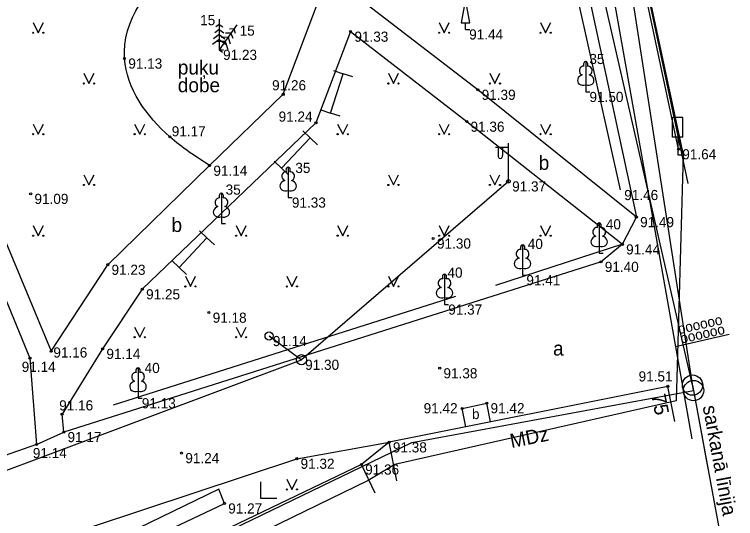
# Model space of a CAD drawing. Extents: x 634272 to 634544, y 247463 to 247653.
# Drawn here: x 634438.83 to 634474.36, y 247516.06 to 247540.9 of the extents above; entities that cross this region are included whole.
import ezdxf

# ---------------------------------------------------------------- set-up
doc = ezdxf.new("R2010")
doc.units = 0
for name, color, linetype in [('APGR_ELEM_####_####_#', 7, 'Continuous'), ('APGR_SARK_####_####_#', 7, 'Continuous'), ('APGR_SARK_####_TKST_#', 7, 'Continuous'), ('APGS_ELEM_####_####_#', 7, 'Continuous'), ('APGS_VADP_ZSPR_####_#', 7, 'Continuous'), ('BUVE_BDET_####_####_#', 7, 'Continuous'), ('BUVE_BDET_####_TKST_#', 7, 'Continuous'), ('BUVE_EKAS_####_####_#', 7, 'Continuous'), ('BUVE_EKAS_ADRS_TKST_#', 7, 'Continuous'), ('BUVE_EKAS_RAKS_TKST_#', 7, 'Continuous'), ('BUVE_SOLS_####_####_#', 7, 'Continuous'), ('CELI_CAPM_####_####_#', 7, 'Continuous'), ('CELI_CMAL_####_####_#', 7, 'Continuous'), ('CELI_CSEG_####_TKST_#', 7, 'Continuous'), ('CELI_ELEM_####_####_#', 7, 'Continuous'), ('CELI_SEGL_####_####_#', 7, 'Continuous'), ('ELEK_ELEM_####_####_#', 7, 'Continuous'), ('ELEK_STUT_####_####_#', 7, 'Continuous'), ('ELEK_VADV_ZSPR_####_#', 7, 'Continuous'), ('NORB_ZOGS_KOKA_####_#', 7, 'Continuous'), ('NORB_ZOGS_ZMET_####_#', 7, 'Continuous'), ('RAMI_UZMR_####_####_#', 7, 'Continuous'), ('RELJ_AATZ_####_TKST_#', 7, 'Continuous'), ('RELJ_ELEM_####_####_#', 7, 'Continuous'), ('ROBZ_PROJ_####_####_#', 7, 'Continuous'), ('ROBZ_UZMR_####_####_#', 7, 'Continuous'), ('SAKK_IZVK_####_TKST_#', 7, 'Continuous'), ('SAKK_KKAN_####_####_#', 7, 'Continuous'), ('TERT_DIAM_####_TKST_#', 7, 'Continuous'), ('TERT_DZOG_####_####_#', 7, 'Continuous'), ('TERT_ELEM_####_####_#', 7, 'Continuous'), ('TERT_IZMT_####_TKST_#', 7, 'Continuous'), ('TERT_KONT_####_####_#', 7, 'Continuous')]:
    doc.layers.add(name, color=color, linetype=linetype)

msp = doc.modelspace()

# ---------------------------------------------------------------- linework, layer by layer
at = {"layer": 'APGR_ELEM_####_####_#'}
for centre in [(634472.24, 247522.64), (634472.29, 247522.37)]:
    msp.add_circle(centre, 0.5, dxfattribs=at)
at = {"layer": 'APGR_SARK_####_####_#'}
for p, q in [((634472.239, 247522.641), (634452.431, 247609.249)), ((634472.285, 247522.369), (634472.997, 247518.53))]:
    msp.add_line(p, q, dxfattribs=at)
msp.add_lwpolyline([(634472.24, 247522.64), (634472.285, 247522.369)], dxfattribs=at)
at = {"layer": 'APGS_ELEM_####_####_#'}
for p, q in [((634463.166, 247532.679), (634463.166, 247534.562)), ((634463.166, 247534.346), (634462.531, 247534.341)), ((634462.666, 247534.342), (634462.666, 247533.95)), ((634462.876, 247534.344), (634462.876, 247533.95))]:
    msp.add_line(p, q, dxfattribs=at)
msp.add_circle((634463.166, 247532.679), 0.09, dxfattribs=at)
msp.add_ellipse((634462.771, 247533.95), major_axis=(0, 0.151), ratio=0.695971, start_param=1.570796, end_param=4.712389, dxfattribs=at)
at = {"layer": 'APGS_VADP_ZSPR_####_#'}
msp.add_lwpolyline([(634463.166, 247532.679), (634452.967, 247523.892)], dxfattribs=at)
at = {"layer": 'BUVE_BDET_####_####_#'}
for p, q in [((634462.287, 247520.826), (634462.101, 247521.751)), ((634461.07, 247520.582), (634460.888, 247521.491))]:
    msp.add_line(p, q, dxfattribs=at)
for points in [[(634460.888, 247521.491), (634462.101, 247521.751)], [(634442.961, 247513.867), (634449.175, 247516.814), (634448.89, 247517.508), (634442.673, 247514.485), (634442.961, 247513.867)]]:
    msp.add_lwpolyline(points, dxfattribs=at)
at = {"layer": 'BUVE_EKAS_####_####_#'}
for p, q in [((634471.371, 247520.855), (634471.025, 247522.579)), ((634457.668, 247517.931), (634457.288, 247519.823)), ((634456.604, 247517.313), (634455.924, 247518.731))]:
    msp.add_line(p, q, dxfattribs=at)
for points in [[(634471.025, 247522.579), (634457.288, 247519.823)], [(634455.924, 247518.731), (634433.316, 247507.888)]]:
    msp.add_lwpolyline(points, dxfattribs=at)
at = {"layer": 'BUVE_SOLS_####_####_#'}
for p, q in [((634454.542, 247538.134), (634455.018, 247537.981)), ((634455.494, 247537.828), (634455.018, 247537.981)), ((634453.919, 247536.196), (634454.395, 247536.043)), ((634454.871, 247535.89), (634454.395, 247536.043)), ((634454.871, 247535.89), (634454.395, 247536.043)), ((634453.041, 247535.164), (634453.403, 247534.82)), ((634453.765, 247534.476), (634453.403, 247534.82)), ((634451.629, 247533.678), (634451.991, 247533.334)), ((634452.353, 247532.99), (634451.991, 247533.334)), ((634447.947, 247530.237), (634448.312, 247529.896)), ((634448.677, 247529.555), (634448.312, 247529.896)), ((634446.577, 247528.771), (634446.942, 247528.43)), ((634447.307, 247528.089), (634446.942, 247528.43))]:
    msp.add_line(p, q, dxfattribs=at)
for points in [[(634454.395, 247536.043), (634455.018, 247537.981)], [(634451.991, 247533.334), (634453.403, 247534.82)], [(634446.942, 247528.43), (634448.312, 247529.896)]]:
    msp.add_lwpolyline(points, dxfattribs=at)
at = {"layer": 'CELI_CAPM_####_####_#'}
for points in [[(634463.467, 247557.413), (634465.341, 247550.039), (634461.38, 247548.991), (634462.172, 247545.409), (634466.133, 247546.478), (634469.47, 247530.921)], [(634468.781, 247529.576), (634467.729, 247528.716)], [(634467.729, 247528.716), (634441.257, 247520.329)], [(634439.91, 247519.719), (634429.724, 247516.149)]]:
    msp.add_lwpolyline(points, dxfattribs=at)
at = {"layer": 'CELI_CMAL_####_####_#'}
for points in [[(634472.031, 247532.571), (634469.381, 247545.11), (634466.419, 247558.939), (634461.107, 247582.724), (634454.551, 247609.343)], [(634448.962, 247545.329), (634432.293, 247544.34), (634440.634, 247524.306)], [(634440.634, 247524.306), (634443.425, 247528.573), (634448.443, 247533.452), (634452.075, 247536.966), (634453.755, 247541.439)], [(634469.47, 247530.921), (634461.663, 247537.193), (634455.996, 247541.547)], [(634455.391, 247540.056), (634453.685, 247535.561), (634445.128, 247527.364), (634443.172, 247524.429), (634441.171, 247521.203)], [(634455.391, 247540.056), (634461.114, 247535.622), (634468.781, 247529.576)], [(634435.216, 247534.576), (634439.591, 247523.962)], [(634439.591, 247523.962), (634439.91, 247519.719)], [(634441.257, 247520.329), (634441.171, 247521.203)], [(634432.152, 247511.13), (634442.666, 247515.679), (634452.74, 247519.016), (634457.288, 247519.823)]]:
    msp.add_lwpolyline(points, dxfattribs=at)
at = {"layer": 'CELI_ELEM_####_####_#'}
for p, q in [((634471.76, 247535.832), (634471.26, 247535.832)), ((634471.26, 247534.863), (634471.26, 247535.832)), ((634471.76, 247534.863), (634471.76, 247535.832)), ((634471.76, 247534.863), (634471.26, 247534.863)), ((634471.514, 247534.863), (634471.514, 247533.985)), ((634471.514, 247533.985), (634471.829, 247533.985))]:
    msp.add_line(p, q, dxfattribs=at)
at = {"layer": 'CELI_SEGL_####_####_#'}
for points in [[(634468.781, 247529.576), (634469.47, 247530.921)], [(634439.91, 247519.719), (634441.257, 247520.329)]]:
    msp.add_lwpolyline(points, dxfattribs=at)
at = {"layer": 'ELEK_ELEM_####_####_#'}
for centre, radius in [((634451.373, 247525.062), 0.2), ((634452.967, 247523.892), 0.25)]:
    msp.add_circle(centre, radius, dxfattribs=at)
at = {"layer": 'ELEK_STUT_####_####_#'}
msp.add_lwpolyline([(634451.373, 247525.062), (634452.967, 247523.892)], dxfattribs=at)
at = {"layer": 'ELEK_VADV_ZSPR_####_#'}
msp.add_lwpolyline([(634425.403, 247513.565), (634452.967, 247523.892)], dxfattribs=at)
at = {"layer": 'NORB_ZOGS_KOKA_####_#'}
msp.add_lwpolyline([(634457.288, 247519.823), (634455.924, 247518.731)], dxfattribs=at)
at = {"layer": 'NORB_ZOGS_ZMET_####_#'}
msp.add_lwpolyline([(634471.548, 247534.262), (634466.407, 247558.475)], dxfattribs=at)
at = {"layer": 'RAMI_UZMR_####_####_#'}
msp.add_lwpolyline([(634466.614, 247558.36), (634469.076, 247546.545), (634471.781, 247533.982), (634471.429, 247521.859), (634457.577, 247518.735), (634456.257, 247517.942), (634433.742, 247506.986), (634428.158, 247503.509), (634420.457, 247500.517), (634407.71, 247496.821), (634397.043, 247493.687), (634395.968, 247498.053), (634390.559, 247517.942), (634387.41, 247527.318), (634427.834, 247538.059), (634425.364, 247546.393), (634376.048, 247532.596), (634371.988, 247530.992)], dxfattribs=at)
at = {"layer": 'RELJ_ELEM_####_####_#'}
for centre in [(634455.391, 247540.056), (634444.251, 247538.733), (634452.075, 247536.966), (634461.663, 247537.193), (634453.685, 247535.561), (634461.114, 247535.622), (634446.479, 247534.873), (634471.548, 247534.262), (634448.443, 247533.452), (634439.626, 247532.065), (634469.47, 247530.921), (634459.461, 247529.864), (634468.781, 247529.576), (634443.425, 247528.573), (634467.729, 247528.716), (634445.128, 247527.364), (634448.409, 247526.212), (634440.634, 247524.306), (634443.172, 247524.429), (634439.591, 247523.962), (634459.78, 247523.472), (634471.025, 247522.579), (634462.101, 247521.751), (634460.888, 247521.491), (634441.171, 247521.203), (634441.257, 247520.329), (634439.91, 247519.719), (634457.288, 247519.823), (634447.06, 247519.294), (634452.74, 247519.016), (634455.924, 247518.731), (634449.175, 247516.814)]:
    msp.add_circle(centre, 0.05, dxfattribs=at)
at = {"layer": 'ROBZ_PROJ_####_####_#'}
msp.add_lwpolyline([(634472.285, 247522.369), (634466.305, 247560.948)], dxfattribs=at)
at = {"layer": 'ROBZ_UZMR_####_####_#'}
for points in [[(634458.415, 247519.805), (634472.285, 247522.369)], [(634472.285, 247522.369), (634473.767, 247514.38)], [(634434.292, 247508.17), (634458.415, 247519.805)]]:
    msp.add_lwpolyline(points, dxfattribs=at)
at = {"layer": 'SAKK_IZVK_####_TKST_#'}
msp.add_line((634471.394, 247524.543), (634474.052, 247525.142), dxfattribs=at)
at = {"layer": 'SAKK_KKAN_####_####_#'}
msp.add_lwpolyline([(634452.888, 247611.435), (634454.857, 247603.576), (634466.565, 247551.758), (634472.201, 247519.993)], dxfattribs=at)
at = {"layer": 'TERT_DZOG_####_####_#'}
for points in [[(634468.687, 247532.255), (634465.596, 247546.127)], [(634468.781, 247529.576), (634462.526, 247527.553)], [(634460.556, 247526.999), (634443.688, 247521.659)]]:
    msp.add_lwpolyline(points, dxfattribs=at)
at = {"layer": 'TERT_ELEM_####_####_#'}
for p, q in [((634448.921, 247540.661), (634448.921, 247539.161)), ((634439.75, 247540.5), (634440, 247540)), ((634440, 247540), (634440.25, 247540.5)), ((634448.921, 247540.161), (634448.705, 247540.003)), ((634448.921, 247540.411), (634448.745, 247540.283)), ((634448.921, 247540.411), (634449.095, 247540.283)), ((634449.781, 247540.39), (634448.921, 247539.161)), ((634448.921, 247540.161), (634449.137, 247540.003)), ((634449.638, 247540.185), (634449.42, 247540.181)), ((634449.638, 247540.185), (634449.707, 247539.98)), ((634459.75, 247540.5), (634460, 247540)), ((634460, 247540), (634460.25, 247540.5)), ((634461.048, 247540.167), (634461.048, 247540.487)), ((634461.048, 247540.167), (634461.258, 247540.167)), ((634464.75, 247540.5), (634465, 247540)), ((634465, 247540), (634465.25, 247540.5)), ((634448.921, 247539.911), (634448.643, 247539.707)), ((634448.921, 247539.911), (634449.199, 247539.707)), ((634449.495, 247539.98), (634449.227, 247539.975)), ((634449.495, 247539.98), (634449.581, 247539.727)), ((634448.921, 247539.661), (634448.589, 247539.417)), ((634449.208, 247539.571), (634448.796, 247539.561)), ((634448.921, 247539.661), (634449.255, 247539.417)), ((634449.351, 247539.775), (634449.006, 247539.768)), ((634449.208, 247539.571), (634449.341, 247539.179)), ((634449.351, 247539.775), (634449.462, 247539.449)), ((634448.921, 247539.161), (634449.121, 247539.161)), ((634448.921, 247539.161), (634449.085, 247539.046)), ((634442.25, 247538), (634442.5, 247537.5)), ((634442.5, 247537.5), (634442.75, 247538)), ((634457.25, 247538), (634457.5, 247537.5)), ((634457.5, 247537.5), (634457.75, 247538)), ((634462.25, 247538), (634462.5, 247537.5)), ((634462.5, 247537.5), (634462.75, 247538)), ((634466.975, 247537.433), (634466.975, 247537.086)), ((634466.975, 247537.086), (634467.175, 247537.086)), ((634439.75, 247535.5), (634440, 247535)), ((634440, 247535), (634440.25, 247535.5)), ((634444.75, 247535.5), (634445, 247535)), ((634445, 247535), (634445.25, 247535.5)), ((634454.75, 247535.5), (634455, 247535)), ((634455, 247535), (634455.25, 247535.5)), ((634459.75, 247535.5), (634460, 247535)), ((634460, 247535), (634460.25, 247535.5)), ((634464.75, 247535.5), (634465, 247535)), ((634465, 247535), (634465.25, 247535.5)), ((634442.25, 247533), (634442.5, 247532.5)), ((634442.5, 247532.5), (634442.75, 247533)), ((634457.25, 247533), (634457.5, 247532.5)), ((634457.5, 247532.5), (634457.75, 247533)), ((634462.25, 247533), (634462.5, 247532.5)), ((634462.5, 247532.5), (634462.75, 247533)), ((634452.312, 247532.229), (634452.312, 247531.882)), ((634452.312, 247531.882), (634452.512, 247531.882)), ((634449.023, 247530.941), (634449.023, 247530.594)), ((634449.023, 247530.594), (634449.223, 247530.594)), ((634439.75, 247530.5), (634440, 247530)), ((634440, 247530), (634440.25, 247530.5)), ((634449.75, 247530.5), (634450, 247530)), ((634450, 247530), (634450.25, 247530.5)), ((634454.75, 247530.5), (634455, 247530)), ((634455, 247530), (634455.25, 247530.5)), ((634459.75, 247530.5), (634460, 247530)), ((634460, 247530), (634460.25, 247530.5)), ((634464.75, 247530.5), (634465, 247530)), ((634465, 247530), (634465.25, 247530.5)), ((634467.639, 247529.484), (634467.639, 247529.137)), ((634467.639, 247529.137), (634467.839, 247529.137)), ((634463.865, 247528.405), (634463.865, 247528.058)), ((634447.25, 247528), (634447.5, 247527.5)), ((634447.5, 247527.5), (634447.75, 247528)), ((634452.25, 247528), (634452.5, 247527.5)), ((634452.5, 247527.5), (634452.75, 247528)), ((634457.25, 247528), (634457.5, 247527.5)), ((634457.5, 247527.5), (634457.75, 247528)), ((634463.865, 247528.058), (634464.065, 247528.058)), ((634460.017, 247526.96), (634460.017, 247526.613)), ((634460.017, 247526.613), (634460.217, 247526.613)), ((634444.75, 247525.5), (634445, 247525)), ((634445, 247525), (634445.25, 247525.5)), ((634449.75, 247525.5), (634450, 247525)), ((634450, 247525), (634450.25, 247525.5)), ((634444.916, 247522.345), (634444.916, 247521.998)), ((634444.916, 247521.998), (634445.116, 247521.998)), ((634450.957, 247517.875), (634450.957, 247517.075)), ((634452.25, 247518), (634452.5, 247517.5)), ((634452.5, 247517.5), (634452.75, 247518)), ((634450.957, 247517.075), (634451.757, 247517.075))]:
    msp.add_line(p, q, dxfattribs=at)
msp.add_lwpolyline([(634460.838, 247540.487), (634461.258, 247540.487), (634461.048, 247541.667)], close=True, dxfattribs=at)
for points in [[(634466.975, 247538.586), (634466.975, 247537.433)], [(634467.065, 247538.354), (634467.064, 247538.355)], [(634452.312, 247533.382), (634452.312, 247532.229)], [(634452.402, 247533.15), (634452.401, 247533.151)], [(634449.023, 247532.094), (634449.023, 247530.941)], [(634449.113, 247531.862), (634449.112, 247531.863)], [(634467.639, 247530.637), (634467.639, 247529.484)], [(634467.729, 247530.405), (634467.728, 247530.406)], [(634463.865, 247529.558), (634463.865, 247528.405)], [(634463.955, 247529.326), (634463.954, 247529.327)], [(634460.017, 247528.113), (634460.017, 247526.96)], [(634460.107, 247527.881), (634460.106, 247527.882)], [(634444.916, 247523.498), (634444.916, 247522.345)], [(634445.006, 247523.266), (634445.005, 247523.267)]]:
    msp.add_lwpolyline(points, dxfattribs=at)
for centre, radius in [((634439.75, 247540), 0.028), ((634440.25, 247540), 0.0263), ((634459.75, 247540), 0.028), ((634460.25, 247540), 0.0263), ((634464.75, 247540), 0.028), ((634465.25, 247540), 0.0263), ((634442.25, 247537.5), 0.028), ((634442.75, 247537.5), 0.0263), ((634457.25, 247537.5), 0.028), ((634457.75, 247537.5), 0.0263), ((634462.25, 247537.5), 0.028), ((634462.75, 247537.5), 0.0263), ((634439.75, 247535), 0.028), ((634440.25, 247535), 0.0263), ((634444.75, 247535), 0.028), ((634445.25, 247535), 0.0263), ((634454.75, 247535), 0.028), ((634455.25, 247535), 0.0263), ((634459.75, 247535), 0.028), ((634460.25, 247535), 0.0263), ((634464.75, 247535), 0.028), ((634465.25, 247535), 0.0263), ((634442.25, 247532.5), 0.028), ((634442.75, 247532.5), 0.0263), ((634457.25, 247532.5), 0.028), ((634457.75, 247532.5), 0.0263), ((634462.25, 247532.5), 0.028), ((634462.75, 247532.5), 0.0263), ((634439.75, 247530), 0.028), ((634440.25, 247530), 0.0263), ((634449.75, 247530), 0.028), ((634450.25, 247530), 0.0263), ((634454.75, 247530), 0.028), ((634455.25, 247530), 0.0263), ((634459.75, 247530), 0.028), ((634460.25, 247530), 0.0263), ((634464.75, 247530), 0.028), ((634465.25, 247530), 0.0263), ((634447.25, 247527.5), 0.028), ((634447.75, 247527.5), 0.0263), ((634452.25, 247527.5), 0.028), ((634452.75, 247527.5), 0.0263), ((634457.25, 247527.5), 0.028), ((634457.75, 247527.5), 0.0263), ((634444.75, 247525), 0.028), ((634445.25, 247525), 0.0263), ((634449.75, 247525), 0.028), ((634450.25, 247525), 0.0263), ((634452.25, 247517.5), 0.028), ((634452.75, 247517.5), 0.0263)]:
    msp.add_circle(centre, radius, dxfattribs=at)
for centre, major_axis, ratio, start_param, end_param in [((634466.975, 247538.436), (0, -0.15), 0.707107, 3.14537, 5.287485), ((634466.975, 247538.436), (0, -0.15), 0.707107, 0.995701, 3.137816), ((634466.847, 247538.141), (-0.039, -0.212), 0.861323, 3.141593, 6.283185), ((634467.103, 247538.141), (0.039, -0.212), 0.861323, 0, 3.141593), ((634466.885, 247537.679), (0.307, 0.095), 0.814445, 1.570796, 4.752015), ((634467.065, 247537.679), (-0.307, 0.095), 0.814445, 1.531171, 4.712389), ((634452.184, 247532.937), (-0.039, -0.212), 0.861323, 3.141593, 6.283185), ((634452.312, 247533.232), (0, -0.15), 0.707107, 3.14537, 5.287485), ((634452.312, 247533.232), (0, -0.15), 0.707107, 0.995701, 3.137816), ((634452.44, 247532.937), (0.039, -0.212), 0.861323, 0, 3.141593), ((634452.222, 247532.475), (0.307, 0.095), 0.814445, 1.570796, 4.752015), ((634452.402, 247532.475), (-0.307, 0.095), 0.814445, 1.531171, 4.712389), ((634449.023, 247531.944), (0, -0.15), 0.707107, 3.14537, 5.287485), ((634449.023, 247531.944), (0, -0.15), 0.707107, 0.995701, 3.137816), ((634448.895, 247531.649), (-0.039, -0.212), 0.861323, 3.141593, 6.283185), ((634449.151, 247531.649), (0.039, -0.212), 0.861323, 0, 3.141593), ((634448.933, 247531.187), (0.307, 0.095), 0.814445, 1.570796, 4.752015), ((634449.113, 247531.187), (-0.307, 0.095), 0.814445, 1.531171, 4.712389), ((634467.639, 247530.487), (0, -0.15), 0.707107, 3.14537, 5.287485), ((634467.639, 247530.487), (0, -0.15), 0.707107, 0.995701, 3.137816), ((634467.511, 247530.192), (-0.039, -0.212), 0.861323, 3.141593, 6.283185), ((634467.767, 247530.192), (0.039, -0.212), 0.861323, 0, 3.141593), ((634467.549, 247529.73), (0.307, 0.095), 0.814445, 1.570796, 4.752015), ((634467.729, 247529.73), (-0.307, 0.095), 0.814445, 1.531171, 4.712389), ((634463.865, 247529.408), (0, -0.15), 0.707107, 3.14537, 5.287485), ((634463.865, 247529.408), (0, -0.15), 0.707107, 0.995701, 3.137816), ((634463.737, 247529.113), (-0.039, -0.212), 0.861323, 3.141593, 6.283185), ((634463.993, 247529.113), (0.039, -0.212), 0.861323, 0, 3.141593), ((634463.775, 247528.651), (0.307, 0.095), 0.814445, 1.570796, 4.752015), ((634463.955, 247528.651), (-0.307, 0.095), 0.814445, 1.531171, 4.712389), ((634460.017, 247527.963), (0, -0.15), 0.707107, 3.14537, 5.287485), ((634460.017, 247527.963), (0, -0.15), 0.707107, 0.995701, 3.137816), ((634459.889, 247527.668), (-0.039, -0.212), 0.861323, 3.141593, 6.283185), ((634460.145, 247527.668), (0.039, -0.212), 0.861323, 0, 3.141593), ((634459.927, 247527.206), (0.307, 0.095), 0.814445, 1.570796, 4.752015), ((634460.107, 247527.206), (-0.307, 0.095), 0.814445, 1.531171, 4.712389), ((634444.916, 247523.348), (0, -0.15), 0.707107, 3.14537, 5.287485), ((634444.916, 247523.348), (0, -0.15), 0.707107, 0.995701, 3.137816), ((634444.788, 247523.053), (-0.039, -0.212), 0.861323, 3.141593, 6.283185), ((634445.044, 247523.053), (0.039, -0.212), 0.861323, 0, 3.141593), ((634444.826, 247522.591), (0.307, 0.095), 0.814445, 1.570796, 4.752015), ((634445.006, 247522.591), (-0.307, 0.095), 0.814445, 1.531171, 4.712389)]:
    msp.add_ellipse(centre, major_axis=major_axis, ratio=ratio, start_param=start_param, end_param=end_param, dxfattribs=at)
at = {"layer": 'TERT_KONT_####_####_#'}
msp.add_spline([(634448.443, 247533.452), (634446.479, 247534.873), (634444.251, 247538.733), (634447.111, 247543.417), (634448.673, 247544.455), (634448.962, 247545.329)], degree=3, dxfattribs=at)

# ---------------------------------------------------------------- texts
at = {"layer": 'APGR_SARK_####_TKST_#'}
msp.add_text('sarkanā līnija', height=0.7, rotation=280.5112, dxfattribs=at).set_placement((634472.736, 247521.586))
at = {"layer": 'BUVE_BDET_####_TKST_#'}
msp.add_text('b', height=0.5, dxfattribs=at).set_placement((634461.371, 247520.966))
at = {"layer": 'BUVE_EKAS_ADRS_TKST_#'}
msp.add_text('75', height=0.7, rotation=281.3444, dxfattribs=at).set_placement((634470.205, 247522.134))
at = {"layer": 'BUVE_EKAS_RAKS_TKST_#'}
msp.add_text('MDz', height=0.7, rotation=11.3444, dxfattribs=at).set_placement((634463.317, 247519.535))
at = {"layer": 'CELI_CSEG_####_TKST_#'}
for s, p in [('b', (634464.659, 247533.245)), ('b', (634446.567, 247530.184)), ('a', (634465.366, 247524.096))]:
    msp.add_text(s, height=0.7, dxfattribs=at).set_placement(p)
at = {"layer": 'RELJ_AATZ_####_TKST_#'}
for s, p in [(' 91.44', (634461.048, 247539.667)), (' 91.44', (634461.048, 247539.667)), (' 91.33', (634455.391, 247539.556)), (' 91.23', (634448.921, 247538.661)), (' 91.13', (634444.251, 247538.233)), (' 91.26', (634451.336, 247537.162)), (' 91.39', (634461.663, 247536.693)), (' 91.50', (634466.975, 247536.586)), (' 91.24', (634451.657, 247535.618)), (' 91.36', (634461.114, 247535.122)), (' 91.17', (634446.392, 247534.895)), (' 91.64', (634471.548, 247533.762)), (' 91.14', (634448.443, 247532.952)), (' 91.37', (634463.166, 247532.179)), (' 91.09', (634439.626, 247531.565)), (' 91.46', (634468.687, 247531.755)), (' 91.33', (634452.312, 247531.382)), (' 91.49', (634469.47, 247530.421)), (' 91.30', (634459.461, 247529.364)), (' 91.44', (634468.781, 247529.076)), (' 91.23', (634443.425, 247528.073)), (' 91.40', (634467.729, 247528.216)), (' 91.41', (634463.865, 247527.558)), (' 91.25', (634445.128, 247526.864)), (' 91.37', (634460.017, 247526.113)), (' 91.18', (634448.409, 247525.712)), (' 91.14', (634451.373, 247524.562)), (' 91.16', (634440.558, 247523.997)), (' 91.14', (634443.172, 247523.929)), (' 91.30', (634452.967, 247523.392)), (' 91.14', (634438.998, 247523.29)), (' 91.38', (634459.78, 247522.972)), (' 91.51', (634469.396, 247522.819)), (' 91.16', (634440.846, 247521.392)), (' 91.13', (634444.916, 247521.498)), (' 91.42', (634458.804, 247521.251)), (' 91.42', (634462.101, 247521.251)), (' 91.17', (634441.257, 247519.829)), (' 91.14', (634439.547, 247519.043)), (' 91.38', (634457.288, 247519.323)), (' 91.24', (634447.06, 247518.794)), (' 91.32', (634452.74, 247518.516)), (' 91.36', (634455.924, 247518.231)), (' 91.27', (634449.175, 247516.314))]:
    msp.add_text(s, height=0.5, dxfattribs=at).set_placement(p)
at = {"layer": 'SAKK_IZVK_####_TKST_#'}
for p in [(634471.571, 247525.151), (634471.693, 247524.685)]:
    msp.add_text('oooooo', height=0.5, rotation=12.6975, dxfattribs=at).set_placement(p)
at = {"layer": 'TERT_DIAM_####_TKST_#'}
for s, p in [('15', (634447.977, 247540.372)), ('15', (634449.923, 247539.855)), ('35', (634467.155, 247538.457)), ('35', (634452.666, 247533.092)), ('35', (634449.232, 247532.022)), ('40', (634467.967, 247530.314)), ('40', (634464.121, 247529.347)), ('40', (634460.163, 247527.932)), ('40', (634445.242, 247523.235))]:
    msp.add_text(s, height=0.5, dxfattribs=at).set_placement(p)
at = {"layer": 'TERT_IZMT_####_TKST_#'}
for s, p in [('puķu', (634446.877, 247537.942)), ('dobe', (634446.877, 247537.07))]:
    msp.add_text(s, height=0.7, dxfattribs=at).set_placement(p)

doc.saveas('drawing.dxf')
